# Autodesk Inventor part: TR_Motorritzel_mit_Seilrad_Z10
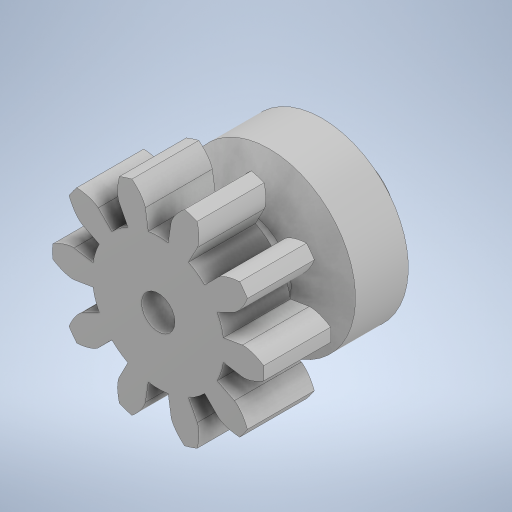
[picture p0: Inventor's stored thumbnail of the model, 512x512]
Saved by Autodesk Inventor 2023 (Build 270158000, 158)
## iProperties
Created: 2023-11
Part Number: TR_Motorritzel_mit_Seilrad_Z10
Material: PBT-Kunststoff
Document SubType Name: Modeling
Designer: AdminForWorker
Density: 1.31 g/cm^3
Appearance: Glatt - Weiß
Title: Component1
Author: AdminForWorker
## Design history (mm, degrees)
feature "Body1"
sketch "Skizze1"
  geometry: L1 (0, 0)-(-3.2, 0); L2 (-3.2, 0)-(-2.5, -1.25); L3 (-2.5, -1.25)-(-4.9, -2.5); L4 (-4.9, -2.5)-(-4.9, -5.5); L5 (-4.9, -5.5)-(-2.4, -5.5); L6 (-2.4, -5.5)-(-2.4, -7.3); L7 (-2.4, -7.3)-(0, -7.3); L8 (0, 0)-(0, -7.3); L9 (0.374, 0)-(-0.374, 0) reference; 1 further point
  constraints: 16 end point, 4 perpendicular, 1 horizontal, 1 midpoint, 1 vertical
  dimensions: "d0" = 7.3 distance of L1.start L7.end; "d1" = 3.2 distance of L1.start L1.end; "d2" = 2.5 horizontal distance of L1.start L2.end; "d3" = 1.25 vertical distance of L1.end L2.end; "d4" = 5.5 vertical distance of L4.end L1.end; "d5" = 3 distance of L3.end L4.end; "d6" = 2.4 distance of L6.end L7.end; "d7" = 4.9 horizontal distance of L4.end L7.end
revolve "Umdrehung1" sketch "Skizze1" stored, may be unused: angle "d8" = 90 deg
sketch "Skizze2"
  geometry: C1 r 2.5 at (0, 0) reference; C2 r 0.95 at (0, 0); 1 further point
  constraints: 1 centre point, 1 coincident
  dimensions: "d9" = 1.9 diameter of C2
extrude "Extrusion1" cut sketch "Skizze2" extent not by distance; stored distance "d10" = 0; taper "d11" = 0 deg
body "Solid1"
